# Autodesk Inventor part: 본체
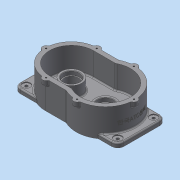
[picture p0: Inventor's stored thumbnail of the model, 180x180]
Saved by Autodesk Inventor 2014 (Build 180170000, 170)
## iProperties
Created: 2025-09
Part Number: 본체
Material: 일반
Document SubType Name: Modeling
Designer: dg
Density: 1 g/cm^3
Appearance: 기본값
Mass: 584.528 g
Surface Area: 1291.41 cm^2
Volume: 584.528 cm^3
Author: dg
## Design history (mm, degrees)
sketch "스케치1"
  geometry: L1 (-118.5, -55)-(118.5, -55); L2 (118.5, -55)-(118.5, 55); L3 (118.5, 55)-(-118.5, 55); L4 (-118.5, 55)-(-118.5, -55); 3 further points
  constraints: 8 end point, 2 midpoint, 2 parallel, 1 horizontal, 1 horizontal alignment, 1 perpendicular, 1 vertical alignment
  dimensions: "d0" = 237 distance of L2.end L3.end; "d1" = 110 distance of L3.end L1.start
extrude "돌출1" new body sketch "스케치1" distance "d2" = 10; taper "d3" = 0 deg
fillet "모깎기1" dims "d4" = 14
hole "구멍1" diameter "d7" = 6.6; stored, may be unused: countersink angle "d11" = 90 deg, drill point angle "d13" = 118 deg; dims "d5" = 10, "d6" = 10, "d8" = 6, "d9" = 18, "d10" = 2, "d12" = 8
hole "구멍2" diameter "d16" = 6.6; stored, may be unused: countersink angle "d20" = 90 deg, drill point angle "d22" = 118 deg; dims "d14" = 10, "d15" = 10, "d17" = 6, "d18" = 18, "d19" = 2, "d21" = 8
hole "구멍3" diameter "d25" = 6.6; stored, may be unused: countersink angle "d29" = 90 deg, drill point angle "d31" = 118 deg; dims "d23" = 10, "d24" = 10, "d26" = 6, "d27" = 18, "d28" = 2, "d30" = 8
hole "구멍4" diameter "d34" = 6.6; stored, may be unused: countersink angle "d38" = 90 deg, drill point angle "d40" = 118 deg; dims "d32" = 10, "d33" = 10, "d35" = 6, "d36" = 18, "d37" = 2, "d39" = 8
sketch "스케치2"
  geometry: L1 (104.5, 55)-(-104.5, 55) reference; L2 (-104.5, -55)-(104.5, -55) reference; L3 (-118.5, 41)-(-118.5, -41) reference; L4 (118.5, -41)-(118.5, 41) reference; L5 (-42.5, 50)-(8.132, 50); L6 (-42.5, -50)-(8.132, -50); L7 (5.684, 60)-(-42.5, 60); L8 (-42.5, -60)-(5.684, -60); A1 r 50 centre (-42.5, 0) between (-42.5, 50) and (-42.5, -50); A2 r 57 centre (35.5, 0) between (8.132, -50) and (8.132, 50); A3 r 60 centre (-42.5, 0) between (-42.5, 60) and (-42.5, -60); A4 r 67 centre (35.5, 0) between (5.684, -60) and (5.684, 60); 1 further point
  constraints: 8 end point, 8 point on circle, 4 centre point, 2 parallel, 2 tangent, 1 horizontal alignment, 1 perpendicular, 1 vertical alignment, 3 other
  dimensions: "d41" = 78 distance of A2.centre A1.centre; "d43" = 50 radius of A1; "d44" = 57 radius of A2; "d45" = 10 distance between parallel lines of L7 L5; "d117" = 76 distance from line of L3 A1.centre
extrude "돌출2" join sketch "스케치2" distance "d46" = 10; taper "d47" = 0 deg
extrude "돌출3" join sketch "스케치2" distance "d48" = 64; taper "d49" = 0 deg
sketch "스케치3"
  geometry: L1 (5.684, 60)-(-42.5, 60) reference; L2 (-42.5, -60)-(5.684, -60) reference; A1 r 57 centre (35.5, 0) between (8.132, -50) and (8.132, 50) reference; A2 r 50 centre (-42.5, 0) between (-42.5, 50) and (-42.5, -50) reference; A3 r 60 centre (-42.5, 0) between (-42.5, 60) and (-42.5, -60) reference; A4 r 67 centre (35.5, 0) between (5.684, -60) and (5.684, 60) reference; A5 r 8 centre (-42.5, 58) between (-34.754, 60) and (-50.361, 59.483); A6 r 8 centre (-100.5, 0) between (-101.983, 7.861) and (-101.983, -7.861); A7 r 8 centre (-42.5, -58) between (-50.361, -59.483) and (-34.754, -60); A8 r 8 centre (35.5, -65) between (27.649, -66.538) and (43.351, -66.538); A9 r 8 centre (35.5, 65) between (43.351, 66.538) and (27.649, 66.538); A10 r 8 centre (100.5, 0) between (102.038, -7.851) and (102.038, 7.851); 7 further points
  constraints: 22 point on circle, 6 centre point, 6 coincident, 5 equal radius, 3 vertical alignment, 2 horizontal alignment, 2 point on line
  dimensions: "d104" = 58 distance of A2.centre point (-100.5, 0); "d105" = 116 distance of point (-42.5, -58) point (-42.5, 58); "d106" = 58 distance of A2.centre point (-42.5, 58); "d107" = 130 distance of point (35.5, -65) point (35.5, 65); "d108" = 65 distance of A1.centre point (35.5, -65); "d109" = 65 horizontal distance of point (100.5, 0) point (35.5, -65); "d119" = 8 radius of A5; "d120" = 78 horizontal distance of point (35.5, 65) point (-42.5, 58)
sketch "스케치6"
  geometry: C1 r 15 at (-35.5, 0) reference; C2 r 17.5 at (-35.5, 0); A1 r 67 centre (-35.5, 0) between (-5.684, 60) and (-73.762, 55) reference; 1 further point
  constraints: 1 centre point, 1 coincident
  dimensions: "d83" = 35 diameter of C2
extrude "돌출12" cut sketch "스케치6" distance "d84" = 8.3; taper "d85" = 0 deg
chamfer "모따기2" distance "d89" = 0.8; stored, may be unused: second distance "d90" = 2, angle "d91" = 30 deg
fillet "모깎기2" dims "d92" = 0.3
fillet "모깎기3" dims "d93" = 3
fillet "모깎기5" dims "d95" = 3
fillet "모깎기6" dims "d96" = 3
fillet "모깎기7" dims "d97" = 13
fillet "모깎기8" dims "d98" = 3
sketch "스케치7"
  geometry: L1 (-7, 0)-(-7, 82) reference; L2 (0, 0)-(0, 82) reference; L3 (-35, 7.5)-(-35, 74.5); L4 (-35, 74.5)-(-25, 74.5); L5 (-25, 74.5)-(-25, 7.5); L6 (-25, 7.5)-(-35, 7.5); 5 further points
  constraints: 3 midpoint, 2 horizontal alignment, 1 horizontal, 1 vertical alignment, 2 other
  dimensions: "d99" = 30 distance from line of L2 point (-30, 41); "d100" = 67 distance of L3.start L3.end; "d101" = 10 distance of L3.end L4.end
feature "엠보싱1" sketch "스케치7" dims "d102" = 0.5, "d103" = 0
hole "구멍6" sketch "스케치3" diameter "d110" = 3.242; stored, may be unused: countersink angle "d114" = 90 deg, drill point angle "d116" = 118 deg; dims "d111" = 8, "d112" = 18, "d113" = 2, "d115" = 10
extrude "돌출13" join sketch "스케치3" distance "d121" = 12; taper "d122" = 0 deg
fillet "모깎기10" dims "d123" = 3
fillet "모깎기11" dims "d124" = 3
node "작업 평면3"
sketch "스케치8"
  geometry: C1 r 16 at (-42.5, 0); C2 r 23.5 at (-42.5, 0); C3 r 18.5 at (-42.5, 0); C4 r 14 at (-42.5, 0); A1 r 50 centre (-42.5, 0) between (-42.5, 50) and (-42.5, -50) reference; 1 further point
  constraints: 4 centre point, 3 coincident, 1 concentric
  dimensions: "d126" = 47 diameter of C2; "d127" = 37 diameter of C3; "d128" = 32 diameter of C1; "d129" = 28 diameter of C4
extrude "돌출14" join sketch "스케치8" stored distance "d130" = 12; taper "d131" = 0 deg
node "작업 평면4"
sketch "스케치9"
  geometry: C1 r 23.5 at (35.5, 0); C2 r 18.5 at (35.5, 0); C3 r 15 at (35.5, 0); A1 r 57 centre (35.5, 0) between (10.654, -51.3) and (10.654, 51.3) reference; 1 further point
  constraints: 3 centre point, 2 coincident, 1 concentric
  dimensions: "d144" = 47 diameter of C1; "d145" = 37 diameter of C2; "d146" = 30 diameter of C3
extrude "돌출18" join sketch "스케치9" stored distance "d147" = 28; taper "d148" = 0 deg
extrude "돌출19" cut sketch "스케치9" distance "d149" = 9; taper "d150" = 0 deg
extrude "돌출20" cut sketch "스케치9" stored distance "d151" = 9; taper "d152" = 0 deg
sketch "스케치10"
  geometry: C1 r 17.962 at (-35.5, 0) reference; C2 r 17.5 at (-35.5, 0); 1 further point
  constraints: 1 centre point, 1 coincident
  dimensions: "d153" = 35 diameter of C2
extrude "돌출21" cut sketch "스케치10" distance "d154" = 8.3; taper "d155" = 0 deg
extrude "돌출22" cut sketch "스케치8" distance "d156" = 9; taper "d157" = 0 deg
extrude "돌출23" cut sketch "스케치8" distance "d158" = 25; taper "d159" = 0 deg
extrude "돌출24" cut sketch "스케치8" distance "d160" = 28; taper "d161" = 0 deg
fillet "모깎기14" dims "d162" = 0.3
fillet "모깎기15" dims "d163" = 0.3
chamfer "모따기4" distance "d164" = 1; stored, may be unused: second distance "d165" = 2, angle "d166" = 30 deg
chamfer "모따기5" distance "d167" = 1; stored, may be unused: second distance "d168" = 2, angle "d169" = 30 deg
fillet "모깎기16" dims "d170" = 3
fillet "모깎기17" dims "d171" = 0.3
node "솔리드1"
other parameters: "d125" = -28, "d143" = -42
